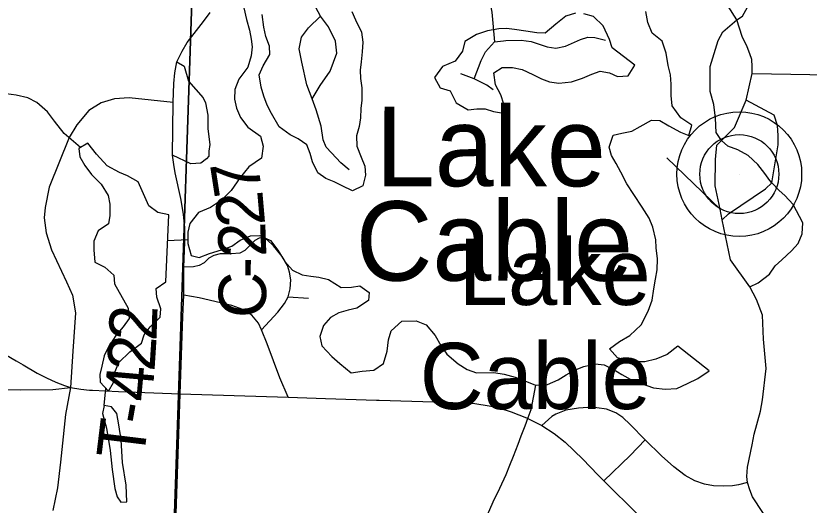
# Model space of a CAD drawing. Extents: x 0 to 34, y 0 to 22.
# Drawn here: x 7.099 to 8.046, y 17.244 to 17.828 of the extents above; entities that cross this region are included whole.
import ezdxf

# ---------------------------------------------------------------- set-up
doc = ezdxf.new("R2010")
doc.units = 0
for name, color, linetype in [('GM_X_Corporation', 7, 'Continuous'), ('GM_X_County_Road', 7, 'Continuous'), ('GM_X_County_Road_Text', 7, 'Continuous'), ('GM_X_Major_Lake', 7, 'Continuous'), ('GM_X_Major_Lake_Text', 7, 'Continuous'), ('GM_X_Minor_Lake', 7, 'Continuous'), ('GM_X_Minor_River', 7, 'Continuous'), ('GM_X_State_Route', 7, 'Continuous'), ('GM_X_Township_Road', 7, 'Continuous'), ('GM_X_Township_Road_Text', 7, 'Continuous'), ('GM_X_Unincorporated', 7, 'Continuous'), ('GM_X_Unincorporated_Location', 7, 'Continuous'), ('GM_X_Unincorporated_Text', 7, 'Continuous')]:
    doc.layers.add(name, color=color, linetype=linetype)

msp = doc.modelspace()

# ---------------------------------------------------------------- linework, layer by layer
at = {"layer": 'GM_X_Corporation'}
for points in [[(7.30996, 17.88061), (7.27561, 16.87038), (6.24525, 16.90712), (6.2808, 17.91168)], [(8.30127, 17.84453), (8.26687, 16.83772), (7.27561, 16.87038), (7.30996, 17.88061)]]:
    msp.add_lwpolyline(points, close=True, dxfattribs=at)
at = {"layer": 'GM_X_County_Road'}
msp.add_line((7.29508, 17.37743), (7.29825, 17.46946), dxfattribs=at)
msp.add_lwpolyline([(7.29825, 17.46946), (7.29914, 17.49502), (7.29939, 17.52828), (7.30062, 17.5581), (7.30034, 17.57517), (7.29896, 17.59172), (7.29559, 17.61035), (7.28884, 17.64087), (7.28725, 17.6508), (7.28587, 17.66198), (7.28636, 17.72462), (7.28726, 17.74752), (7.28849, 17.7601), (7.29107, 17.77321), (7.29718, 17.78583), (7.30322, 17.79648), (7.32256, 17.82132), (7.33054, 17.83232)], dxfattribs=at)
at = {"layer": 'GM_X_Major_Lake'}
for points in [[(7.3708, 17.83757), (7.37402, 17.82393), (7.37761, 17.81107), (7.37965, 17.80046), (7.38091, 17.79098), (7.37954, 17.78032), (7.37555, 17.76696), (7.36474, 17.75275), (7.35998, 17.74015), (7.35976, 17.72875), (7.36218, 17.71814), (7.36688, 17.70681), (7.37576, 17.69554), (7.3907, 17.68473), (7.3939, 17.67261), (7.39182, 17.65853), (7.37679, 17.64806), (7.36634, 17.63537), (7.35593, 17.61965), (7.34432, 17.60809), (7.33116, 17.59954), (7.31682, 17.59364), (7.30638, 17.58058), (7.30386, 17.57028), (7.30405, 17.55661), (7.30804, 17.54223), (7.31756, 17.5397), (7.33001, 17.54482), (7.34436, 17.5492), (7.35644, 17.55355), (7.36659, 17.56053), (7.37866, 17.56563), (7.39004, 17.56617), (7.40263, 17.56027), (7.41152, 17.54862), (7.41967, 17.53506), (7.42891, 17.52493), (7.44037, 17.51901), (7.45101, 17.51764), (7.46051, 17.51625), (7.47193, 17.51375), (7.48686, 17.50408), (7.49937, 17.50464), (7.50921, 17.50592), (7.52032, 17.49809), (7.51969, 17.48859), (7.50578, 17.47927), (7.49557, 17.47723), (7.48423, 17.47403), (7.47444, 17.46819), (7.46585, 17.45857), (7.46147, 17.44559), (7.4639, 17.43461), (7.47583, 17.42186), (7.48543, 17.41326), (7.49886, 17.40242), (7.51211, 17.40413), (7.52613, 17.40547), (7.5374, 17.41361), (7.54175, 17.4281), (7.54346, 17.44181), (7.54674, 17.45249), (7.55947, 17.46407), (7.57654, 17.46431), (7.58837, 17.45953), (7.59916, 17.44677), (7.60615, 17.43509), (7.61312, 17.42455), (7.62656, 17.41296), (7.63727, 17.40627), (7.64871, 17.40225), (7.66919, 17.40254), (7.68173, 17.40081), (7.69468, 17.3972), (7.70612, 17.3928), (7.71908, 17.38766), (7.73311, 17.38824), (7.74593, 17.39412), (7.75572, 17.39995), (7.7655, 17.40541), (7.77645, 17.40974), (7.79006, 17.41297), (7.8007, 17.41198), (7.81177, 17.40682), (7.8221, 17.40013), (7.83548, 17.39271), (7.84501, 17.38943), (7.85987, 17.38432), (7.87355, 17.38261), (7.88758, 17.38357), (7.9004, 17.38945), (7.91283, 17.3957)], [(7.49984, 17.8333), (7.50414, 17.82348), (7.51117, 17.80876), (7.51286, 17.79663), (7.51225, 17.78522), (7.51089, 17.77342), (7.50989, 17.76353), (7.51003, 17.75327), (7.5117, 17.74228), (7.51152, 17.72746), (7.51051, 17.71757), (7.51029, 17.70654), (7.50853, 17.69626), (7.50527, 17.68482), (7.50581, 17.67266), (7.51092, 17.65944), (7.51524, 17.64886), (7.51614, 17.63823), (7.5129, 17.62527), (7.50046, 17.6194), (7.48825, 17.62531), (7.4787, 17.63011), (7.46878, 17.63415), (7.4592, 17.64086), (7.45296, 17.65407), (7.45016, 17.66391), (7.44623, 17.67411), (7.43551, 17.68156), (7.42596, 17.68636), (7.41294, 17.69568), (7.404, 17.71151), (7.39855, 17.72169), (7.39461, 17.73228), (7.39143, 17.74287), (7.38933, 17.75766), (7.39374, 17.76836), (7.4019, 17.78215)], [(7.4019, 17.78215), (7.40139, 17.79202), (7.39706, 17.80336), (7.39463, 17.81473), (7.39291, 17.8299)], [(7.76656, 17.83134), (7.75522, 17.82777), (7.74321, 17.8181), (7.73046, 17.80766), (7.72059, 17.8079), (7.70729, 17.81), (7.69398, 17.81171), (7.68448, 17.81309), (7.675, 17.81258), (7.66176, 17.81012), (7.64854, 17.80575), (7.63462, 17.79758), (7.63174, 17.78614), (7.62317, 17.77424), (7.60809, 17.76757), (7.5984, 17.75451), (7.60502, 17.74245), (7.61721, 17.73882), (7.62423, 17.72448), (7.63876, 17.71595), (7.64898, 17.71723), (7.65885, 17.71737), (7.66875, 17.71409), (7.67826, 17.71232), (7.68116, 17.72262), (7.67759, 17.73397), (7.67136, 17.74566), (7.66927, 17.76007), (7.67904, 17.76666), (7.69156, 17.76646), (7.70298, 17.76396), (7.71558, 17.75806), (7.72627, 17.75289), (7.7358, 17.7496), (7.74682, 17.74786), (7.76197, 17.74959), (7.77519, 17.75396), (7.78613, 17.75867), (7.79595, 17.76223), (7.80736, 17.76011), (7.8169, 17.75568), (7.82941, 17.75662), (7.83758, 17.76927)], [(7.81036, 17.79017), (7.80719, 17.8), (7.79977, 17.81623), (7.78823, 17.82747), (7.77681, 17.83073)], [(7.88879, 17.43412), (7.87603, 17.42406), (7.86244, 17.41855), (7.84959, 17.41533), (7.83972, 17.41557), (7.82642, 17.41728), (7.8169, 17.42019), (7.80727, 17.43107), (7.81929, 17.4396), (7.83171, 17.44699), (7.84519, 17.45972), (7.85332, 17.47579), (7.85808, 17.48878), (7.86017, 17.50249), (7.86229, 17.51391), (7.86403, 17.52534), (7.86461, 17.53826), (7.86292, 17.55154), (7.86241, 17.56103), (7.85879, 17.57618), (7.85447, 17.58675), (7.84633, 17.59994), (7.83626, 17.61499), (7.82812, 17.6278), (7.82072, 17.64175), (7.81527, 17.65194), (7.80983, 17.66174), (7.80704, 17.67158), (7.81178, 17.6857), (7.82199, 17.68813), (7.8341, 17.69057), (7.84389, 17.69603), (7.85744, 17.70382), (7.86731, 17.7032), (7.87801, 17.69689), (7.89215, 17.68949), (7.90207, 17.68545), (7.90532, 17.69765), (7.8923, 17.70659), (7.88186, 17.72088), (7.88094, 17.73303), (7.88075, 17.7467), (7.88023, 17.75771), (7.87742, 17.76907), (7.87494, 17.78348), (7.8702, 17.79784), (7.8583, 17.80756), (7.8532, 17.82002), (7.85075, 17.83329)], [(7.83758, 17.76927), (7.81036, 17.79017)], [(7.92637, 17.40463), (7.88879, 17.43412)], [(7.91283, 17.3957), (7.92637, 17.40463)]]:
    msp.add_lwpolyline(points, dxfattribs=at)
at = {"layer": 'GM_X_Minor_Lake'}
for points in [[(7.2812, 17.59086), (7.26827, 17.59372), (7.25754, 17.60155), (7.25127, 17.6159), (7.24463, 17.63024), (7.23202, 17.63729), (7.22248, 17.64133), (7.20796, 17.64911), (7.19487, 17.66298), (7.18483, 17.67614), (7.17391, 17.66991), (7.17518, 17.66005), (7.18102, 17.64949), (7.18913, 17.63896), (7.20066, 17.62735), (7.20881, 17.61378), (7.21085, 17.60355), (7.21104, 17.58988), (7.20927, 17.57998), (7.19687, 17.57182), (7.19173, 17.55921), (7.19186, 17.54895), (7.1932, 17.53416), (7.20504, 17.52824), (7.21579, 17.5189), (7.2167, 17.50827), (7.23302, 17.47962), (7.23395, 17.4671), (7.22687, 17.45712), (7.21791, 17.44673), (7.209, 17.43255), (7.2042, 17.42261), (7.20133, 17.41041), (7.19919, 17.4005), (7.19932, 17.391), (7.20932, 17.3805), (7.21525, 17.39084), (7.21625, 17.40112), (7.22176, 17.41449), (7.23487, 17.42722), (7.24876, 17.43767), (7.25204, 17.44759), (7.25912, 17.45719), (7.2711, 17.46876), (7.27173, 17.47865), (7.26698, 17.49264), (7.26609, 17.50288), (7.27774, 17.51065)], [(7.27774, 17.51065), (7.2812, 17.59086)], [(7.20425, 17.36334), (7.2021, 17.35381), (7.20689, 17.33639), (7.21143, 17.30948), (7.21363, 17.2871), (7.21697, 17.26435), (7.21976, 17.25451), (7.22402, 17.24811), (7.23123, 17.24821), (7.23057, 17.26834), (7.22604, 17.29525), (7.22453, 17.3222), (7.22163, 17.3404), (7.21917, 17.35367), (7.213, 17.36156)], [(7.213, 17.36156), (7.20425, 17.36334)]]:
    msp.add_lwpolyline(points, dxfattribs=at)
at = {"layer": 'GM_X_Minor_River'}
for points in [[(7.17602, 17.67111), (7.1566, 17.6879), (7.14502, 17.70256), (7.13652, 17.71345), (7.12385, 17.72468), (7.11315, 17.73023), (7.09907, 17.73345), (7.08729, 17.73518)], [(7.27987, 17.55999), (7.30398, 17.56151)], [(7.20425, 17.36334), (7.20628, 17.3837)], [(7.71908, 17.38766), (7.71625, 17.3728), (7.71341, 17.35832), (7.70975, 17.34877), (7.70609, 17.33884), (7.70132, 17.32662), (7.69767, 17.31669), (7.69217, 17.30255), (7.68776, 17.29185), (7.68336, 17.28077), (7.676, 17.26433), (7.66787, 17.24788), (7.66125, 17.23259)]]:
    msp.add_lwpolyline(points, dxfattribs=at)
at = {"layer": 'GM_X_State_Route'}
for points in [[(6.40832, 17.64736), (6.45964, 17.64539), (6.51823, 17.64324), (6.6044, 17.63997), (6.66688, 17.63768), (6.67953, 17.63698), (6.69135, 17.63601), (6.70078, 17.63478), (6.7107, 17.63316), (6.72161, 17.63038), (6.73117, 17.62732), (6.74072, 17.62346), (6.75083, 17.6185), (6.76115, 17.61307), (6.82009, 17.57888), (6.885, 17.54108), (6.94445, 17.50685), (6.98584, 17.48273), (7.05471, 17.44243), (7.09926, 17.4165), (7.10732, 17.41186)], [(7.10732, 17.41186), (7.12435, 17.40205), (7.13519, 17.39635), (7.14638, 17.39114), (7.15673, 17.38724), (7.16385, 17.38499), (7.17624, 17.38283), (7.18674, 17.38169), (7.19019, 17.38152)], [(7.19019, 17.38152), (7.22128, 17.38002), (7.29508, 17.37743), (7.42369, 17.37329), (7.46844, 17.37182), (7.52932, 17.36984), (7.53232, 17.36974)], [(7.53232, 17.36974), (7.61032, 17.36716), (7.63016, 17.36657), (7.64639, 17.3656), (7.66355, 17.36296), (7.67648, 17.35997), (7.68989, 17.35586), (7.70831, 17.34878), (7.72634, 17.33929), (7.74107, 17.33009), (7.75432, 17.31978), (7.77544, 17.29937), (7.79346, 17.28064)], [(7.79346, 17.28064), (7.80039, 17.27344), (7.84143, 17.23298), (7.88139, 17.19708), (7.98069, 17.10817), (8.13192, 16.97351), (8.25032, 16.86785), (8.3168, 16.80825)]]:
    msp.add_lwpolyline(points, dxfattribs=at)
at = {"layer": 'GM_X_Township_Road'}
for p, q in [((7.93916, 17.5975), (7.87584, 17.65862)), ((7.42377, 17.49311), (7.44815, 17.49119)), ((7.29305, 17.31725), (7.29508, 17.37743))]:
    msp.add_line(p, q, dxfattribs=at)
for points in [[(7.32289, 18.12545), (7.37247, 18.11064), (7.3976, 18.10544), (7.40759, 18.10581), (7.42911, 18.10655), (7.44899, 18.10446), (7.47234, 18.10113), (7.49083, 18.09835), (7.5025, 18.09473), (7.52419, 18.08431), (7.5695, 18.05484), (7.60036, 18.03566), (7.61231, 18.0251), (7.61787, 18.01564), (7.62635, 17.99646), (7.63079, 17.97395), (7.6333, 17.93906), (7.63649, 17.91654), (7.64136, 17.89958), (7.65387, 17.87651), (7.66123, 17.86067), (7.66401, 17.84732), (7.66679, 17.83245), (7.66985, 17.79715)], [(7.49661, 17.64462), (7.48656, 17.65276), (7.47543, 17.66472), (7.46913, 17.67165), (7.4655, 17.68006), (7.46314, 17.69642), (7.45706, 17.71588), (7.45238, 17.72924), (7.4621, 17.74501), (7.47373, 17.76227), (7.48204, 17.78375), (7.48039, 17.79782), (7.472, 17.81504), (7.4623, 17.82778), (7.44889, 17.85317), (7.42955, 17.88226), (7.41979, 17.89717), (7.41248, 17.90324), (7.40547, 17.90702), (7.39699, 17.9093), (7.38418, 17.91133), (7.35925, 17.91389), (7.34437, 17.91643)], [(7.94081, 17.67942), (7.93445, 17.68881), (7.93356, 17.70593), (7.93189, 17.72232), (7.92754, 17.73805), (7.92749, 17.76767), (7.93694, 17.79885), (7.94261, 17.80891), (7.95907, 17.82345), (7.966, 17.82782), (7.98545, 17.8632)], [(8.00345, 17.2158), (7.97792, 17.25443), (7.9746, 17.26255), (7.97195, 17.27134), (7.97096, 17.27879), (7.97179, 17.28957), (7.97741, 17.31624), (7.97974, 17.32918), (7.98737, 17.3567), (7.98969, 17.36996), (7.9941, 17.4074), (7.99093, 17.44236), (7.98993, 17.47122), (7.98269, 17.48993), (7.9746, 17.50468), (7.95179, 17.53713), (7.94178, 17.58498), (7.93916, 17.5975), (7.93331, 17.62547), (7.93386, 17.65696), (7.93552, 17.674), (7.94081, 17.67942), (7.95643, 17.6949), (7.9703, 17.72764), (7.97756, 17.75952), (7.97766, 17.76788), (7.97711, 17.7762), (7.9749, 17.78285), (7.97158, 17.79115), (7.96549, 17.80335), (7.95907, 17.82345), (7.94872, 17.83981)], [(7.45238, 17.72924), (7.44587, 17.74566), (7.43992, 17.7727), (7.4368, 17.78869), (7.43969, 17.80269), (7.44819, 17.81392), (7.4623, 17.82778)], [(7.64581, 17.75281), (7.65415, 17.77491), (7.65915, 17.78533), (7.66985, 17.79715), (7.68092, 17.79828)], [(7.68092, 17.79828), (7.68347, 17.79854), (7.70196, 17.79909), (7.71377, 17.79742), (7.73282, 17.79117), (7.74324, 17.78964), (7.75478, 17.792), (7.77257, 17.80006), (7.78133, 17.80257), (7.78994, 17.80243), (7.80231, 17.79923)], [(7.29107, 17.77321), (7.29949, 17.76809), (7.30468, 17.75032), (7.32246, 17.73029), (7.32501, 17.72456), (7.32777, 17.70971), (7.32786, 17.69339), (7.33018, 17.67477), (7.32929, 17.66681), (7.32918, 17.66074), (7.32648, 17.65737), (7.3196, 17.65256), (7.3075, 17.65162), (7.28587, 17.66198)], [(7.66832, 17.73988), (7.66082, 17.74544), (7.64581, 17.75281), (7.62996, 17.75892)], [(7.97756, 17.75952), (8.09249, 17.75748), (8.29786, 17.75006)], [(7.28636, 17.72462), (7.23384, 17.73053), (7.21648, 17.72912), (7.20054, 17.72443), (7.186, 17.71505), (7.17146, 17.69816), (7.16255, 17.68315), (7.13863, 17.62358), (7.13393, 17.59966), (7.13252, 17.587), (7.13487, 17.56918), (7.14144, 17.54901), (7.15933, 17.51087), (7.16633, 17.49503), (7.17, 17.47405), (7.16669, 17.42803), (7.16385, 17.38499), (7.15822, 17.35255), (7.15381, 17.31094), (7.15197, 17.29585), (7.14865, 17.26529), (7.14312, 17.23804)], [(7.94178, 17.58498), (7.94946, 17.59181), (7.99331, 17.62178), (8.00111, 17.62913), (8.00846, 17.6744), (8.00849, 17.68542), (8.00778, 17.69721), (8.00369, 17.70951), (7.9703, 17.72764)], [(7.9746, 17.50468), (7.98468, 17.50967), (7.9983, 17.51982), (8.00509, 17.52983), (8.01292, 17.53715), (8.02428, 17.54775), (8.03255, 17.55658), (8.03713, 17.56818), (8.03798, 17.58106), (8.0263, 17.60313), (8.01647, 17.61373), (8.00987, 17.61966), (8.00111, 17.62913), (7.99859, 17.63184), (7.99246, 17.64003), (7.98415, 17.65096), (7.97281, 17.66162), (7.96056, 17.66813), (7.94862, 17.67273), (7.94081, 17.67942)], [(7.39206, 17.45346), (7.41126, 17.47448), (7.41946, 17.48491), (7.42377, 17.49311), (7.426, 17.50256), (7.42676, 17.51333), (7.42523, 17.52243), (7.4228, 17.53036), (7.41648, 17.54092), (7.40619, 17.55385), (7.39889, 17.56087), (7.39417, 17.56323), (7.38902, 17.56309), (7.38381, 17.56017), (7.37846, 17.55468), (7.37221, 17.54808), (7.36595, 17.54502), (7.35629, 17.54419), (7.34274, 17.54419), (7.33496, 17.54245), (7.32891, 17.53925), (7.32342, 17.53362), (7.31751, 17.53022), (7.31098, 17.52855), (7.29939, 17.52828)], [(7.42369, 17.37329), (7.41372, 17.39635), (7.3986, 17.43678), (7.39206, 17.45346), (7.38856, 17.46166), (7.38022, 17.47107), (7.36958, 17.47781), (7.35645, 17.4826), (7.31741, 17.49165), (7.29914, 17.49502)], [(7.02394, 17.38398), (7.10449, 17.38189), (7.14288, 17.38259), (7.16385, 17.38499)], [(7.97195, 17.27134), (7.96134, 17.26851), (7.95405, 17.26752), (7.94286, 17.26719), (7.93153, 17.26757), (7.92059, 17.26952), (7.90912, 17.27362), (7.89752, 17.2798), (7.88396, 17.2903), (7.8693, 17.30343), (7.84967, 17.32256), (7.83205, 17.34075), (7.82322, 17.34902), (7.81499, 17.35448), (7.80366, 17.35879), (7.79205, 17.36038), (7.78146, 17.3608), (7.77016, 17.36028), (7.75522, 17.35781), (7.74327, 17.35309), (7.7384, 17.35017), (7.7343, 17.34648), (7.72634, 17.33929)], [(7.24673, 16.00452), (7.24847, 16.08072), (7.2561, 16.25614), (7.25863, 16.3351), (7.26276, 16.44144), (7.27018, 16.64921), (7.27252, 16.73094), (7.27577, 16.80581), (7.27645, 16.84209), (7.28028, 16.93914), (7.29305, 17.31725)], [(7.80039, 17.27344), (7.83177, 17.30383), (7.84967, 17.32256)]]:
    msp.add_lwpolyline(points, dxfattribs=at)
at = {"layer": 'GM_X_Unincorporated'}
for radius in [0.0744, 0.04716]:
    msp.add_circle((7.96218, 17.63934), radius, dxfattribs=at)
at = {"layer": 'GM_X_Unincorporated_Location'}
msp.add_line((7.96218, 17.63934), (7.96218, 17.63934), dxfattribs=at)

# ---------------------------------------------------------------- texts
at = {"layer": 'GM_X_County_Road_Text'}
for s, rotation, p in [('7', 98.7874, (7.39291, 17.61787)), ('2', 94.95628, (7.39643, 17.57888)), ('2', 92.12523, (7.39792, 17.54085)), ('-', 89.76346, (7.39786, 17.51496)), ('C', 88.84073, (7.39691, 17.4673))]:
    msp.add_text(s, height=0.05682, rotation=rotation, dxfattribs=at).set_placement(p)
at = {"layer": 'GM_X_Major_Lake_Text'}
for s, height, rotation, p in [('Lake', 0.094725, 359.97694, (7.52831, 17.62494)), ('Cable', 0.094724, 359.97696, (7.50441, 17.51227))]:
    msp.add_text(s, height=height, rotation=rotation, dxfattribs=at).set_placement(p)
at = {"layer": 'GM_X_Township_Road_Text'}
for s, rotation, p in [('2', 87.85616, (7.26648, 17.43966)), ('2', 86.33139, (7.26415, 17.40309)), ('4', 84.89677, (7.26092, 17.36668)), ('-', 80.04491, (7.2562, 17.3385)), ('T', 83.09186, (7.2512, 17.2971))]:
    msp.add_text(s, height=0.05682, rotation=rotation, dxfattribs=at).set_placement(p)
at = {"layer": 'GM_X_Unincorporated_Text'}
for s, p in [('Lake', (7.62739, 17.48327)), ('Cable', (7.58073, 17.3591))]:
    msp.add_text(s, height=0.078977, rotation=0.00001, dxfattribs=at).set_placement(p)

doc.saveas('drawing.dxf')
